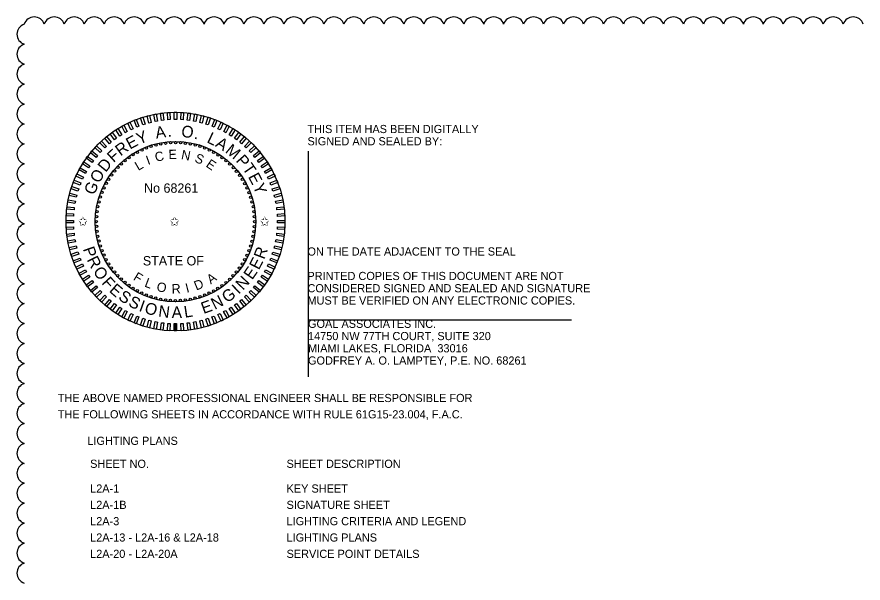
# Model space of a CAD drawing. Extents: x -811 to 10319, y -2309 to 9962.
# Drawn here: x -810.85 to -803.6, y -2208.79 to -2203.94 of the extents above; entities that cross this region are included whole.
import ezdxf

# ---------------------------------------------------------------- set-up
doc = ezdxf.new("R2010")
doc.units = 0
for name, color, linetype in [('AdhocPoint_dp', 7, 'Continuous'), ('PlotBorder_dp', 7, 'Continuous'), ('TextMinor', 7, 'Continuous'), ('TextMisc', 7, 'Continuous'), ('TextShtNo', 7, 'Continuous'), ('TextTitle', 7, 'Continuous')]:
    doc.layers.add(name, color=color, linetype=linetype)

msp = doc.modelspace()

# ---------------------------------------------------------------- linework, layer by layer
at = {"layer": 'AdhocPoint_dp'}
for p, q in [((-808.3546, -2205.0892), (-808.3546, -2207.0239)), ((-808.3546, -2206.5339), (-806.0979, -2206.5339))]:
    msp.add_line(p, q, dxfattribs=at)
at = {"layer": 'TextMinor'}
for radius in [0.9375, 0.6875]:
    msp.add_circle((-809.4901, -2205.6926), radius, dxfattribs=at)
at = {"layer": 'TextShtNo'}
for p, q in [((-809.5001, -2206.6301), (-809.5003, -2206.5676)), ((-809.4901, -2206.6301), (-809.4903, -2206.5676)), ((-809.4801, -2206.6301), (-809.4803, -2206.5676))]:
    msp.add_line(p, q, dxfattribs=at)
for points in [[(-809.7508, -2204.8572), (-809.77, -2204.8635), (-809.7893, -2204.8041), (-809.7701, -2204.7979)], [(-809.6979, -2204.8425), (-809.7174, -2204.8475), (-809.7329, -2204.7871), (-809.7134, -2204.782)], [(-809.6441, -2204.8312), (-809.6639, -2204.8349), (-809.6756, -2204.7736), (-809.6558, -2204.7698)], [(-809.5897, -2204.8232), (-809.6097, -2204.8257), (-809.6175, -2204.7638), (-809.5975, -2204.7612)], [(-809.5349, -2204.8187), (-809.555, -2204.8199), (-809.559, -2204.7576), (-809.5388, -2204.7563)], [(-809.4799, -2204.8176), (-809.5001, -2204.8176), (-809.5001, -2204.7551), (-809.4799, -2204.7551)], [(-809.425, -2204.8199), (-809.4452, -2204.8187), (-809.4412, -2204.7563), (-809.4211, -2204.7576)], [(-809.3703, -2204.8257), (-809.3904, -2204.8232), (-809.3825, -2204.7613), (-809.3625, -2204.7638)], [(-809.3162, -2204.835), (-809.336, -2204.8312), (-809.3243, -2204.7699), (-809.3045, -2204.7736)], [(-809.2626, -2204.8476), (-809.2822, -2204.8426), (-809.2667, -2204.7821), (-809.2471, -2204.7871)], [(-809.21, -2204.8635), (-809.2292, -2204.8573), (-809.2099, -2204.7979), (-809.1907, -2204.8042)], [(-809.9027, -2204.9209), (-809.9204, -2204.9306), (-809.9505, -2204.8759), (-809.9328, -2204.8662)], [(-809.8535, -2204.8965), (-809.8717, -2204.9051), (-809.8983, -2204.8486), (-809.8801, -2204.84)], [(-809.8028, -2204.8753), (-809.8215, -2204.8827), (-809.8445, -2204.8246), (-809.8258, -2204.8172)], [(-809.1585, -2204.8828), (-809.1773, -2204.8753), (-809.1543, -2204.8173), (-809.1355, -2204.8247)], [(-809.1083, -2204.9052), (-809.1266, -2204.8966), (-809.1, -2204.8401), (-809.0817, -2204.8487)], [(-809.0596, -2204.9307), (-809.0773, -2204.921), (-809.0473, -2204.8663), (-809.0296, -2204.876)], [(-809.9962, -2204.9787), (-810.0125, -2204.9906), (-810.0492, -2204.94), (-810.0329, -2204.9282)], [(-809.9504, -2204.9483), (-809.9674, -2204.9591), (-810.0009, -2204.9064), (-809.9838, -2204.8956)], [(-809.0127, -2204.9592), (-809.0297, -2204.9484), (-808.9962, -2204.8957), (-808.9792, -2204.9065)], [(-808.9676, -2204.9907), (-808.9839, -2204.9788), (-808.9472, -2204.9283), (-808.9308, -2204.9402)], [(-810.0817, -2205.0478), (-810.0964, -2205.0616), (-810.1392, -2205.0161), (-810.1244, -2205.0022)], [(-810.04, -2205.0119), (-810.0556, -2205.0247), (-810.0954, -2204.9766), (-810.0798, -2204.9638)], [(-808.9245, -2205.0249), (-808.9401, -2205.012), (-808.9003, -2204.9639), (-808.8847, -2204.9768)], [(-808.8837, -2205.0617), (-808.8984, -2205.0479), (-808.8557, -2205.0024), (-808.841, -2205.0162)], [(-810.1579, -2205.127), (-810.1707, -2205.1425), (-810.2188, -2205.1027), (-810.206, -2205.0872)], [(-810.121, -2205.0862), (-810.1348, -2205.1009), (-810.1804, -2205.0581), (-810.1665, -2205.0434)], [(-808.8453, -2205.101), (-808.8591, -2205.0863), (-808.8136, -2205.0436), (-808.7998, -2205.0583)], [(-808.8094, -2205.1427), (-808.8223, -2205.1271), (-808.7742, -2205.0873), (-808.7613, -2205.1029)], [(-810.192, -2205.17), (-810.2039, -2205.1864), (-810.2544, -2205.1497), (-810.2426, -2205.1333)], [(-808.7762, -2205.1865), (-808.7881, -2205.1702), (-808.7376, -2205.1335), (-808.7257, -2205.1498)], [(-810.252, -2205.2621), (-810.2617, -2205.2798), (-810.3164, -2205.2497), (-810.3067, -2205.232)], [(-810.2235, -2205.2151), (-810.2343, -2205.2322), (-810.287, -2205.1987), (-810.2762, -2205.1817)], [(-808.7459, -2205.2323), (-808.7567, -2205.2153), (-808.7039, -2205.1818), (-808.6931, -2205.1989)], [(-808.7184, -2205.28), (-808.7281, -2205.2623), (-808.6734, -2205.2322), (-808.6637, -2205.2499)], [(-810.2775, -2205.3108), (-810.2861, -2205.3291), (-810.3426, -2205.3025), (-810.334, -2205.2842)], [(-808.694, -2205.3292), (-808.7026, -2205.311), (-808.6461, -2205.2844), (-808.6375, -2205.3027)], [(-810.3, -2205.361), (-810.3074, -2205.3798), (-810.3654, -2205.3568), (-810.358, -2205.338)], [(-808.6728, -2205.3799), (-808.6802, -2205.3612), (-808.6222, -2205.3382), (-808.6147, -2205.357)], [(-810.3351, -2205.4651), (-810.3401, -2205.4847), (-810.4006, -2205.4691), (-810.3956, -2205.4496)], [(-810.3192, -2205.4125), (-810.3254, -2205.4317), (-810.3848, -2205.4124), (-810.3786, -2205.3932)], [(-808.6548, -2205.4319), (-808.661, -2205.4127), (-808.6016, -2205.3934), (-808.5954, -2205.4126)], [(-808.64, -2205.4849), (-808.6451, -2205.4653), (-808.5846, -2205.4498), (-808.5796, -2205.4693)], [(-810.3477, -2205.5186), (-810.3515, -2205.5385), (-810.4129, -2205.5268), (-810.4091, -2205.5069)], [(-808.6287, -2205.5386), (-808.6325, -2205.5188), (-808.5711, -2205.5071), (-808.5673, -2205.5269)], [(-810.357, -2205.5728), (-810.3595, -2205.5928), (-810.4215, -2205.585), (-810.4189, -2205.565)], [(-808.6207, -2205.593), (-808.6232, -2205.573), (-808.5613, -2205.5652), (-808.5588, -2205.5852)], [(-810.3652, -2205.6824), (-810.3652, -2205.7026), (-810.4276, -2205.7026), (-810.4276, -2205.6824)], [(-810.3628, -2205.6275), (-810.3641, -2205.6476), (-810.4264, -2205.6437), (-810.4251, -2205.6236)], [(-808.6162, -2205.6478), (-808.6174, -2205.6277), (-808.5551, -2205.6238), (-808.5539, -2205.6439)], [(-810.3641, -2205.7374), (-810.3628, -2205.7575), (-810.4251, -2205.7614), (-810.4264, -2205.7413)], [(-808.6175, -2205.7577), (-808.6162, -2205.7376), (-808.5539, -2205.7415), (-808.5551, -2205.7616)], [(-808.6151, -2205.7028), (-808.6151, -2205.6826), (-808.5527, -2205.6826), (-808.5527, -2205.7028)], [(-810.3595, -2205.7922), (-810.357, -2205.8122), (-810.4189, -2205.82), (-810.4215, -2205.8)], [(-808.6233, -2205.8124), (-808.6207, -2205.7923), (-808.5588, -2205.8002), (-808.5613, -2205.8202)], [(-810.3516, -2205.8466), (-810.3478, -2205.8664), (-810.4091, -2205.8781), (-810.4129, -2205.8583)], [(-808.6325, -2205.8666), (-808.6287, -2205.8467), (-808.5674, -2205.8584), (-808.5712, -2205.8783)], [(-810.3402, -2205.9003), (-810.3352, -2205.9199), (-810.3957, -2205.9354), (-810.4007, -2205.9159)], [(-810.3255, -2205.9533), (-810.3192, -2205.9725), (-810.3786, -2205.9918), (-810.3849, -2205.9726)], [(-808.6611, -2205.9727), (-808.6548, -2205.9535), (-808.5954, -2205.9728), (-808.6017, -2205.992)], [(-808.6451, -2205.9201), (-808.6401, -2205.9005), (-808.5796, -2205.916), (-808.5846, -2205.9356)], [(-810.3075, -2206.0052), (-810.3, -2206.024), (-810.3581, -2206.047), (-810.3655, -2206.0282)], [(-808.6803, -2206.0242), (-808.6729, -2206.0054), (-808.6148, -2206.0284), (-808.6222, -2206.0472)], [(-810.2862, -2206.0559), (-810.2776, -2206.0742), (-810.3341, -2206.1008), (-810.3427, -2206.0825)], [(-810.2618, -2206.1052), (-810.2521, -2206.1229), (-810.3068, -2206.153), (-810.3165, -2206.1353)], [(-808.7282, -2206.1231), (-808.7185, -2206.1054), (-808.6638, -2206.1355), (-808.6735, -2206.1532)], [(-808.7027, -2206.0744), (-808.6941, -2206.0561), (-808.6376, -2206.0827), (-808.6462, -2206.101)], [(-810.2344, -2206.1529), (-810.2236, -2206.1699), (-810.2763, -2206.2034), (-810.2871, -2206.1863)], [(-808.7568, -2206.1701), (-808.746, -2206.153), (-808.6932, -2206.1865), (-808.704, -2206.2035)], [(-810.204, -2206.1987), (-810.1922, -2206.215), (-810.2427, -2206.2517), (-810.2545, -2206.2354)], [(-810.1708, -2206.2425), (-810.158, -2206.2581), (-810.2061, -2206.2979), (-810.2189, -2206.2823)], [(-808.8224, -2206.2582), (-808.8095, -2206.2427), (-808.7614, -2206.2825), (-808.7743, -2206.298)], [(-808.7882, -2206.2152), (-808.7763, -2206.1988), (-808.7258, -2206.2355), (-808.7377, -2206.2519)], [(-810.135, -2206.2842), (-810.1211, -2206.2989), (-810.1667, -2206.3416), (-810.1805, -2206.3269)], [(-810.0965, -2206.3235), (-810.0818, -2206.3373), (-810.1246, -2206.3828), (-810.1393, -2206.369)], [(-808.8985, -2206.3374), (-808.8838, -2206.3236), (-808.8411, -2206.3691), (-808.8558, -2206.383)], [(-808.8592, -2206.299), (-808.8454, -2206.2843), (-808.7999, -2206.327), (-808.8137, -2206.3418)], [(-810.0557, -2206.3603), (-810.0402, -2206.3732), (-810.08, -2206.4213), (-810.0955, -2206.4084)], [(-810.0127, -2206.3945), (-809.9964, -2206.4064), (-810.0331, -2206.4569), (-810.0494, -2206.445)], [(-808.984, -2206.4065), (-808.9677, -2206.3946), (-808.931, -2206.4451), (-808.9473, -2206.457)], [(-808.9402, -2206.3733), (-808.9247, -2206.3604), (-808.8848, -2206.4086), (-808.9004, -2206.4214)], [(-809.9676, -2206.426), (-809.9505, -2206.4368), (-809.984, -2206.4895), (-810.001, -2206.4787)], [(-809.9206, -2206.4545), (-809.9029, -2206.4642), (-809.933, -2206.5189), (-809.9507, -2206.5092)], [(-809.0775, -2206.4643), (-809.0598, -2206.4546), (-809.0297, -2206.5093), (-809.0474, -2206.519)], [(-809.0299, -2206.4369), (-809.0128, -2206.4261), (-808.9794, -2206.4788), (-808.9964, -2206.4896)], [(-809.8719, -2206.48), (-809.8536, -2206.4886), (-809.8802, -2206.5451), (-809.8985, -2206.5365)], [(-809.8217, -2206.5024), (-809.8029, -2206.5099), (-809.8259, -2206.5679), (-809.8447, -2206.5605)], [(-809.7702, -2206.5217), (-809.751, -2206.5279), (-809.7703, -2206.5873), (-809.7895, -2206.581)], [(-809.7176, -2206.5376), (-809.698, -2206.5426), (-809.7136, -2206.6031), (-809.7331, -2206.5981)], [(-809.6641, -2206.5502), (-809.6443, -2206.554), (-809.656, -2206.6153), (-809.6758, -2206.6116)], [(-809.3362, -2206.554), (-809.3163, -2206.5503), (-809.3046, -2206.6116), (-809.3245, -2206.6154)], [(-809.2824, -2206.5427), (-809.2628, -2206.5376), (-809.2473, -2206.5981), (-809.2668, -2206.6031)], [(-809.2294, -2206.5279), (-809.2102, -2206.5217), (-809.1909, -2206.5811), (-809.2101, -2206.5873)], [(-809.1775, -2206.5099), (-809.1587, -2206.5025), (-809.1357, -2206.5606), (-809.1545, -2206.568)], [(-809.1268, -2206.4887), (-809.1085, -2206.4801), (-809.0819, -2206.5366), (-809.1002, -2206.5452)], [(-809.6099, -2206.5594), (-809.5899, -2206.562), (-809.5977, -2206.6239), (-809.6177, -2206.6214)], [(-809.5552, -2206.5653), (-809.5351, -2206.5665), (-809.539, -2206.6288), (-809.5592, -2206.6276)], [(-809.5003, -2206.5676), (-809.4801, -2206.5676), (-809.4801, -2206.6301), (-809.5003, -2206.6301)], [(-809.4453, -2206.5665), (-809.4252, -2206.5653), (-809.4213, -2206.6276), (-809.4414, -2206.6289)], [(-809.3906, -2206.562), (-809.3705, -2206.5595), (-809.3627, -2206.6214), (-809.3827, -2206.624)]]:
    msp.add_lwpolyline(points, close=True, dxfattribs=at)
for centre in [(-809.6581, -2205.0363), (-809.6165, -2205.027), (-809.5745, -2205.0204), (-809.5321, -2205.0164), (-809.4896, -2205.0151), (-809.447, -2205.0165), (-809.4047, -2205.0205), (-809.3626, -2205.0272), (-809.3211, -2205.0366), (-809.816, -2205.0987), (-809.7781, -2205.0794), (-809.739, -2205.0625), (-809.6989, -2205.0481), (-809.2802, -2205.0485), (-809.2402, -2205.0629), (-809.2012, -2205.0798), (-809.1633, -2205.0992), (-809.9215, -2205.1702), (-809.8879, -2205.1442), (-809.8527, -2205.1203), (-809.1266, -2205.1209), (-809.0915, -2205.1448), (-809.0579, -2205.171), (-809.9836, -2205.2284), (-809.9535, -2205.1984), (-809.026, -2205.1991), (-808.9959, -2205.2292), (-810.0618, -2205.3291), (-810.0379, -2205.2939), (-810.0118, -2205.2603), (-808.9678, -2205.2612), (-808.9417, -2205.2948), (-810.0835, -2205.3657), (-808.9178, -2205.3301), (-808.8962, -2205.3667), (-810.1198, -2205.4427), (-810.1029, -2205.4036), (-808.8769, -2205.4047), (-808.86, -2205.4437), (-810.1462, -2205.5236), (-810.1343, -2205.4827), (-808.8456, -2205.4838), (-808.8338, -2205.5247), (-810.1622, -2205.6071), (-810.1555, -2205.5651), (-808.8245, -2205.5662), (-808.8179, -2205.6082), (-810.1676, -2205.692), (-810.1662, -2205.6495), (-808.814, -2205.6506), (-810.1663, -2205.7346), (-808.814, -2205.7357), (-808.8127, -2205.6932), (-810.1623, -2205.7769), (-810.1557, -2205.819), (-808.8248, -2205.8201), (-808.8181, -2205.7781), (-810.1464, -2205.8605), (-810.1346, -2205.9014), (-808.846, -2205.9025), (-808.8341, -2205.8616), (-810.1202, -2205.9415), (-810.1034, -2205.9805), (-808.8774, -2205.9816), (-808.8604, -2205.9425), (-810.0841, -2206.0185), (-808.8967, -2206.0195), (-810.0624, -2206.0551), (-810.0385, -2206.0903), (-810.0125, -2206.124), (-808.9685, -2206.1249), (-808.9424, -2206.0913), (-808.9184, -2206.0561), (-809.9844, -2206.1559), (-809.9543, -2206.1861), (-809.0268, -2206.1868), (-808.9967, -2206.1568), (-809.9224, -2206.2142), (-809.8888, -2206.2403), (-809.8536, -2206.2643), (-809.1276, -2206.2649), (-809.0924, -2206.241), (-809.0587, -2206.215), (-809.817, -2206.286), (-809.7791, -2206.3053), (-809.74, -2206.3223), (-809.7, -2206.3367), (-809.2813, -2206.3371), (-809.2413, -2206.3227), (-809.2022, -2206.3058), (-809.1642, -2206.2865), (-809.6591, -2206.3486), (-809.6176, -2206.358), (-809.5756, -2206.3647), (-809.5332, -2206.3687), (-809.4901, -2206.3701), (-809.4481, -2206.3688), (-809.4058, -2206.3648), (-809.3637, -2206.3582), (-809.3222, -2206.3489)]:
    msp.add_circle(centre, 0.01, dxfattribs=at)
at = {"layer": 'TextTitle'}
for centre, start, end in [((-810.7002, -2204.0276), 17.5, 162.5), ((-810.5291, -2204.0276), 17.5, 162.5), ((-810.358, -2204.0276), 17.5, 162.5), ((-810.1868, -2204.0276), 17.5, 162.5), ((-810.0157, -2204.0276), 17.5, 162.5), ((-809.8446, -2204.0276), 17.5, 162.5), ((-809.6735, -2204.0276), 17.5, 162.5), ((-809.5024, -2204.0276), 17.5, 162.5), ((-809.3312, -2204.0276), 17.5, 162.5), ((-809.1601, -2204.0276), 17.5, 162.5), ((-808.989, -2204.0276), 17.5, 162.5), ((-808.8179, -2204.0276), 17.5, 162.5), ((-808.6467, -2204.0276), 17.5, 162.5), ((-808.4756, -2204.0276), 17.5, 162.5), ((-808.3045, -2204.0276), 17.5, 162.5), ((-808.1334, -2204.0276), 17.5, 162.5), ((-807.9622, -2204.0276), 17.5, 162.5), ((-807.7911, -2204.0276), 17.5, 162.5), ((-807.62, -2204.0276), 17.5, 162.5), ((-807.4489, -2204.0276), 17.5, 162.5), ((-807.2778, -2204.0276), 17.5, 162.5), ((-807.1066, -2204.0276), 17.5, 162.5), ((-806.9355, -2204.0276), 17.5, 162.5), ((-806.7644, -2204.0276), 17.5, 162.5), ((-806.5933, -2204.0276), 17.5, 162.5), ((-806.4221, -2204.0276), 17.5, 162.5), ((-806.251, -2204.0276), 17.5, 162.5), ((-806.0799, -2204.0276), 17.5, 162.5), ((-805.9088, -2204.0276), 17.5, 162.5), ((-805.7377, -2204.0276), 17.5, 162.5), ((-805.5665, -2204.0276), 17.5, 162.5), ((-805.3954, -2204.0276), 17.5, 162.5), ((-805.2243, -2204.0276), 17.5, 162.5), ((-805.0532, -2204.0276), 17.5, 162.5), ((-804.882, -2204.0276), 17.5, 162.5), ((-804.7109, -2204.0276), 17.5, 162.5), ((-804.5398, -2204.0276), 17.5, 162.5), ((-804.3687, -2204.0276), 17.5, 162.5), ((-804.1976, -2204.0276), 17.5, 162.5), ((-804.0264, -2204.0276), 17.5, 162.5), ((-803.8553, -2204.0276), 17.5, 162.5), ((-803.6842, -2204.0276), 17.5, 162.5), ((-810.7588, -2204.0862), 107.5, 252.5), ((-810.7588, -2204.2573), 107.5, 252.5), ((-810.7588, -2204.4284), 107.5, 252.5), ((-810.7588, -2204.5996), 107.5, 252.5), ((-810.7588, -2204.7707), 107.5, 252.5), ((-810.7588, -2204.9418), 107.5, 252.5), ((-810.7588, -2205.1129), 107.5, 252.5), ((-810.7588, -2205.2841), 107.5, 252.5), ((-810.7588, -2205.4552), 107.5, 252.5), ((-810.7588, -2205.6263), 107.5, 252.5), ((-810.7588, -2205.7974), 107.5, 252.5), ((-810.7588, -2205.9685), 107.5, 252.5), ((-810.7588, -2206.1397), 107.5, 252.5), ((-810.7588, -2206.3108), 107.5, 252.5), ((-810.7588, -2206.4819), 107.5, 252.5), ((-810.7588, -2206.653), 107.5, 252.5), ((-810.7588, -2206.8242), 107.5, 252.5), ((-810.7588, -2206.9953), 107.5, 252.5), ((-810.7588, -2207.1664), 107.5, 252.5), ((-810.7588, -2207.3375), 107.5, 252.5), ((-810.7588, -2207.5087), 107.5, 252.5), ((-810.7588, -2207.6798), 107.5, 252.5), ((-810.7588, -2207.8509), 107.5, 252.5), ((-810.7588, -2208.022), 107.5, 252.5), ((-810.7588, -2208.1931), 107.5, 252.5), ((-810.7588, -2208.3643), 107.5, 252.5), ((-810.7588, -2208.5354), 107.5, 252.5), ((-810.7588, -2208.7065), 107.5, 252.5)]:
    msp.add_arc(centre, 0.0897, start, end, dxfattribs=at)

# ---------------------------------------------------------------- texts
at = {"layer": 'PlotBorder_dp'}
for s, p in [('THIS ITEM HAS BEEN DIGITALLY', (-808.3596, -2204.934)), ('SIGNED AND SEALED BY:', (-808.3596, -2205.039)), ('ON THE DATE ADJACENT TO THE SEAL', (-808.3596, -2205.984)), ('PRINTED COPIES OF THIS DOCUMENT ARE NOT ', (-808.3596, -2206.194)), ('CONSIDERED SIGNED AND SEALED AND SIGNATURE ', (-808.3596, -2206.299)), ('MUST BE VERIFIED ON ANY ELECTRONIC COPIES.', (-808.3596, -2206.404)), ('GOAL ASSOCIATES INC.', (-808.3546, -2206.6039)), ('14750 NW 77TH COURT, SUITE 320', (-808.3546, -2206.7089)), ('MIAMI LAKES, FLORIDA  33016', (-808.3546, -2206.8139)), ('GODFREY A. O. LAMPTEY, P.E. NO. 68261', (-808.3546, -2206.9189)), ('THE ABOVE NAMED PROFESSIONAL ENGINEER SHALL BE RESPONSIBLE FOR ', (-810.4987, -2207.24)), ('THE FOLLOWING SHEETS IN ACCORDANCE WITH RULE 61G15-23.004, F.A.C.', (-810.4987, -2207.38)), ('LIGHTING PLANS', (-810.245, -2207.6071))]:
    msp.add_text(s, height=0.07, dxfattribs=at).set_placement(p)
at = {"layer": 'TextMisc'}
for s, p in [('SHEET NO.', (-810.2215, -2207.8041)), ('SHEET DESCRIPTION', (-808.5387, -2207.8041)), ('L2A-1', (-810.2215, -2208.0162)), ('KEY SHEET', (-808.5387, -2208.0162)), ('L2A-1B', (-810.2215, -2208.1562)), ('SIGNATURE SHEET', (-808.5387, -2208.1562)), ('L2A-3', (-810.2215, -2208.2962)), ('LIGHTING CRITERIA AND LEGEND', (-808.5387, -2208.2962)), ('L2A-13 - L2A-16 & L2A-18', (-810.2215, -2208.4362)), ('LIGHTING PLANS', (-808.5387, -2208.4362)), ('L2A-20 - L2A-20A', (-810.2215, -2208.5762)), ('SERVICE POINT DETAILS', (-808.5387, -2208.5762))]:
    msp.add_text(s, height=0.07, dxfattribs=at).set_placement(p)
at = {"layer": 'TextShtNo'}
for s, height, rotation, p in [('A', 0.1, 8.80884, (-809.6551, -2204.982)), ('O', 0.1, 352.18771, (-809.4449, -2204.9645)), ('E', 0.1, 28.10553, (-809.8806, -2205.0764)), ('Y', 0.1, 21.06329, (-809.8021, -2205.0332)), ('.', 0.1, 1.04184, (-809.5575, -2204.9662)), ('L', 0.1, 334.67271, (-809.2279, -2205.0118)), ('R', 0.1, 35.92688, (-809.9609, -2205.1353)), ('.', 0.1, 343.52684, (-809.3358, -2204.9796)), ('A', 0.1, 328.40959, (-809.1552, -2205.0445)), ('M', 0.1, 320.6426, (-809.0707, -2205.0957)), ('F', 0.1, 42.37723, (-810.0205, -2205.1917)), ('C', 0.08, 12.20255, (-809.6579, -2205.181)), ('E', 0.08, 0.41861, (-809.5498, -2205.1575)), ('N', 0.08, 349.29143, (-809.4455, -2205.1561)), ('D', 0.1, 50.8569, (-810.0886, -2205.2754)), ('I', 0.08, 20.01168, (-809.7258, -2205.2085)), ('S', 0.08, 337.02207, (-809.3325, -2205.1778)), ('E', 0.08, 325.86633, (-809.2358, -2205.218)), ('P', 0.1, 311.19658, (-808.9784, -2205.1727)), ('L', 0.08, 30.40215, (-809.8093, -2205.259)), ('T', 0.1, 304.45632, (-808.9209, -2205.2363)), ('O', 0.1, 59.51777, (-810.1446, -2205.3702)), ('E', 0.1, 297.63152, (-808.8707, -2205.3072)), ('G', 0.1, 68.0518, (-810.1851, -2205.4709)), ('Y', 0.1, 290.58928, (-808.8281, -2205.386)), ('P', 0.1, 289.40551, (-810.2848, -2205.9272)), ('R', 0.1, 69.5134, (-808.7299, -2206.0223)), ('R', 0.1, 296.14576, (-810.2518, -2206.0188)), ('E', 0.1, 62.47116, (-808.7761, -2206.113)), ('O', 0.1, 303.96711, (-810.2003, -2206.1194)), ('E', 0.1, 55.42892, (-808.833, -2206.1974)), ('F', 0.1, 312.62798, (-810.1279, -2206.2215)), ('F', 0.08, 328.72408, (-809.8582, -2206.1892)), ('L', 0.08, 339.29159, (-809.7609, -2206.2483)), ('A', 0.08, 34.49917, (-809.1883, -2206.232)), ('N', 0.1, 47.17876, (-808.9123, -2206.2864)), ('E', 0.1, 319.07833, (-810.0645, -2206.2898)), ('O', 0.08, 349.68206, (-809.6562, -2206.288)), ('R', 0.08, 2.33977, (-809.5217, -2206.3099)), ('I', 0.08, 14.20366, (-809.3941, -2206.3032)), ('D', 0.08, 22.01279, (-809.312, -2206.2845)), ('I', 0.1, 43.64556, (-808.9499, -2206.3209)), ('S', 0.1, 326.12056, (-809.9869, -2206.3557)), ('S', 0.1, 333.193, (-809.9015, -2206.4119)), ('N', 0.1, 26.86136, (-809.1544, -2206.4501)), ('G', 0.1, 35.11153, (-809.0492, -2206.3941)), ('I', 0.1, 340.26543, (-809.8098, -2206.457)), ('O', 0.1, 343.79863, (-809.7621, -2206.4753)), ('E', 0.1, 19.81912, (-809.2498, -2206.4856)), ('N', 0.1, 352.45949, (-809.6411, -2206.5073)), ('A', 0.1, 0.70966, (-809.5227, -2206.5206)), ('L', 0.1, 8.47665, (-809.4105, -2206.5174))]:
    msp.add_text(s, height=height, rotation=rotation, dxfattribs=at).set_placement(p)
for s, p in [('No 68261', (-809.7591, -2205.4454)), ('✩', (-810.3251, -2205.7305)), ('✩', (-809.5404, -2205.7305)), ('✩', (-808.7685, -2205.7305)), ('STATE OF', (-809.7698, -2206.0688))]:
    msp.add_text(s, height=0.08, dxfattribs=at).set_placement(p)

doc.saveas('drawing.dxf')
